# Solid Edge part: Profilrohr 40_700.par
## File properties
Username: ahadarics
Dokumentum tartalom típus: 0
Author: ahadarics
Last saved by: ahadarics
Revision: 95
Sűrűség: 0,000 kg/m^3
Pontosság: 0,990
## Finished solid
Body 1: solid body, 175 faces, 519 edges, 346 vertices.
  Faces by surface: cylinder 107, plane 68
  Edges by curve: line 305, circle 214
Bounding box of the edges (mm): 51.354 x 51.354 x 743.000, from (-25.6768, -25.6768, -634) to (25.6768, 25.6768, 109).
Cylindrical faces by radius (mm): R0.1 x16, R0.2 x30, R0.5 x28, R1 x8, R2.7 x8, R3.5 x4, R5 x4, R20 x1, R22 x8
Planar faces by outward normal: +x 6, +y 6, +z 1, -x 4, -y 4, -z 1, oblique 46
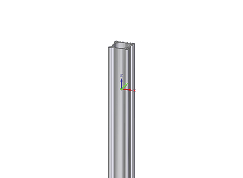
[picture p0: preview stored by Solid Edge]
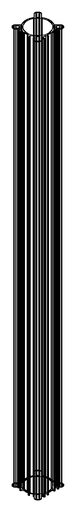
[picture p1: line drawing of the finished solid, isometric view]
